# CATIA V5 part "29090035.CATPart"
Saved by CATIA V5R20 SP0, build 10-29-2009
Part number: 29090035
Definition: NONE
Nomenclature: 29090035
Source: Unknown
Description: 29090035
Bounding box of the stored display mesh (mm): x -17.5 to 44.548, y -59 to 93.548, z -49 to 49
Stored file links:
  C:\Users\Utente\Desktop\IO LAVORO\3D X SITO CF\X SITO\PLASTICA\RF1\29090035.CATPart
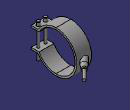
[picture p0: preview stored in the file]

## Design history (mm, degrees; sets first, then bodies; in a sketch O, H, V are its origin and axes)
Body1 "29090035" (main body)
  Solid1: solid without history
